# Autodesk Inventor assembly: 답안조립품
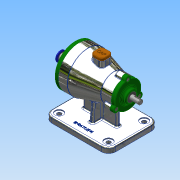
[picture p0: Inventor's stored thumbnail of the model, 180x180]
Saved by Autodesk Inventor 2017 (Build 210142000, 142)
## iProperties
Part Number: 답안조립품
Material: 일반
Document SubType Name: Assembly
Designer: user
Author: user
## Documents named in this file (16)
- C:\Users\user\Desktop\711006V1016\답안조립품.iam
- C:\Users\user\Desktop\711006V1016\본체.ipt
- C:\Users\user\Desktop\711006V1016\앞커버.ipt
- C:\Users\user\Desktop\711006V1016\뒤커버.ipt
- C:\Users\user\Desktop\711006V1016\오일 실 17x30x8.ipt
- C:\Users\user\Desktop\711006V1016\오일 실 10x20x7.ipt
- C:\Users\user\Desktop\711006V1016\베어링 6203.ipt
- C:\Users\user\Desktop\711006V1016\베어링 6200.ipt
- C:\Users\user\Desktop\711006V1016\축.ipt
- C:\Users\user\Desktop\711006V1016\키 5x5.ipt
- 키 5 x 5.ipt
- C:\Users\user\Desktop\711006V1016\스프로킷.ipt
- C:\Users\user\Desktop\711006V1016\마개.ipt
- C:\Users\user\Desktop\711006V1016\와셔.ipt
- C:\Users\user\Desktop\711006V1016\볼트 M4.ipt
- 볼트 M4 x 12.ipt
